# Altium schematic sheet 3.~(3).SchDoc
size 609 x 444 mm
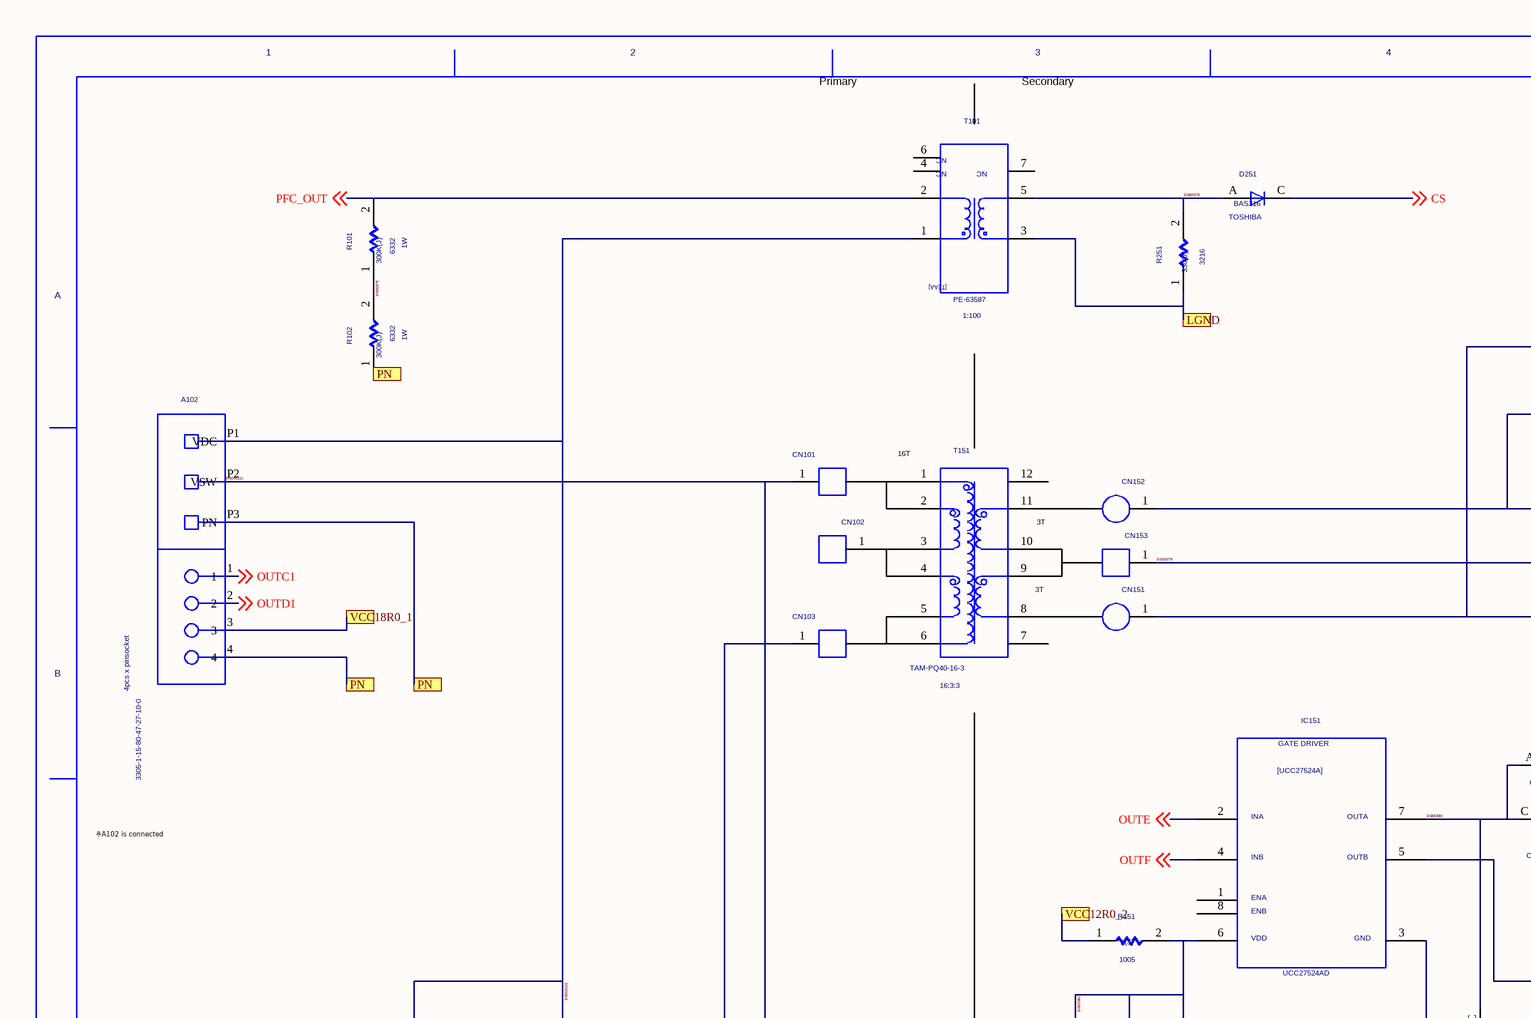
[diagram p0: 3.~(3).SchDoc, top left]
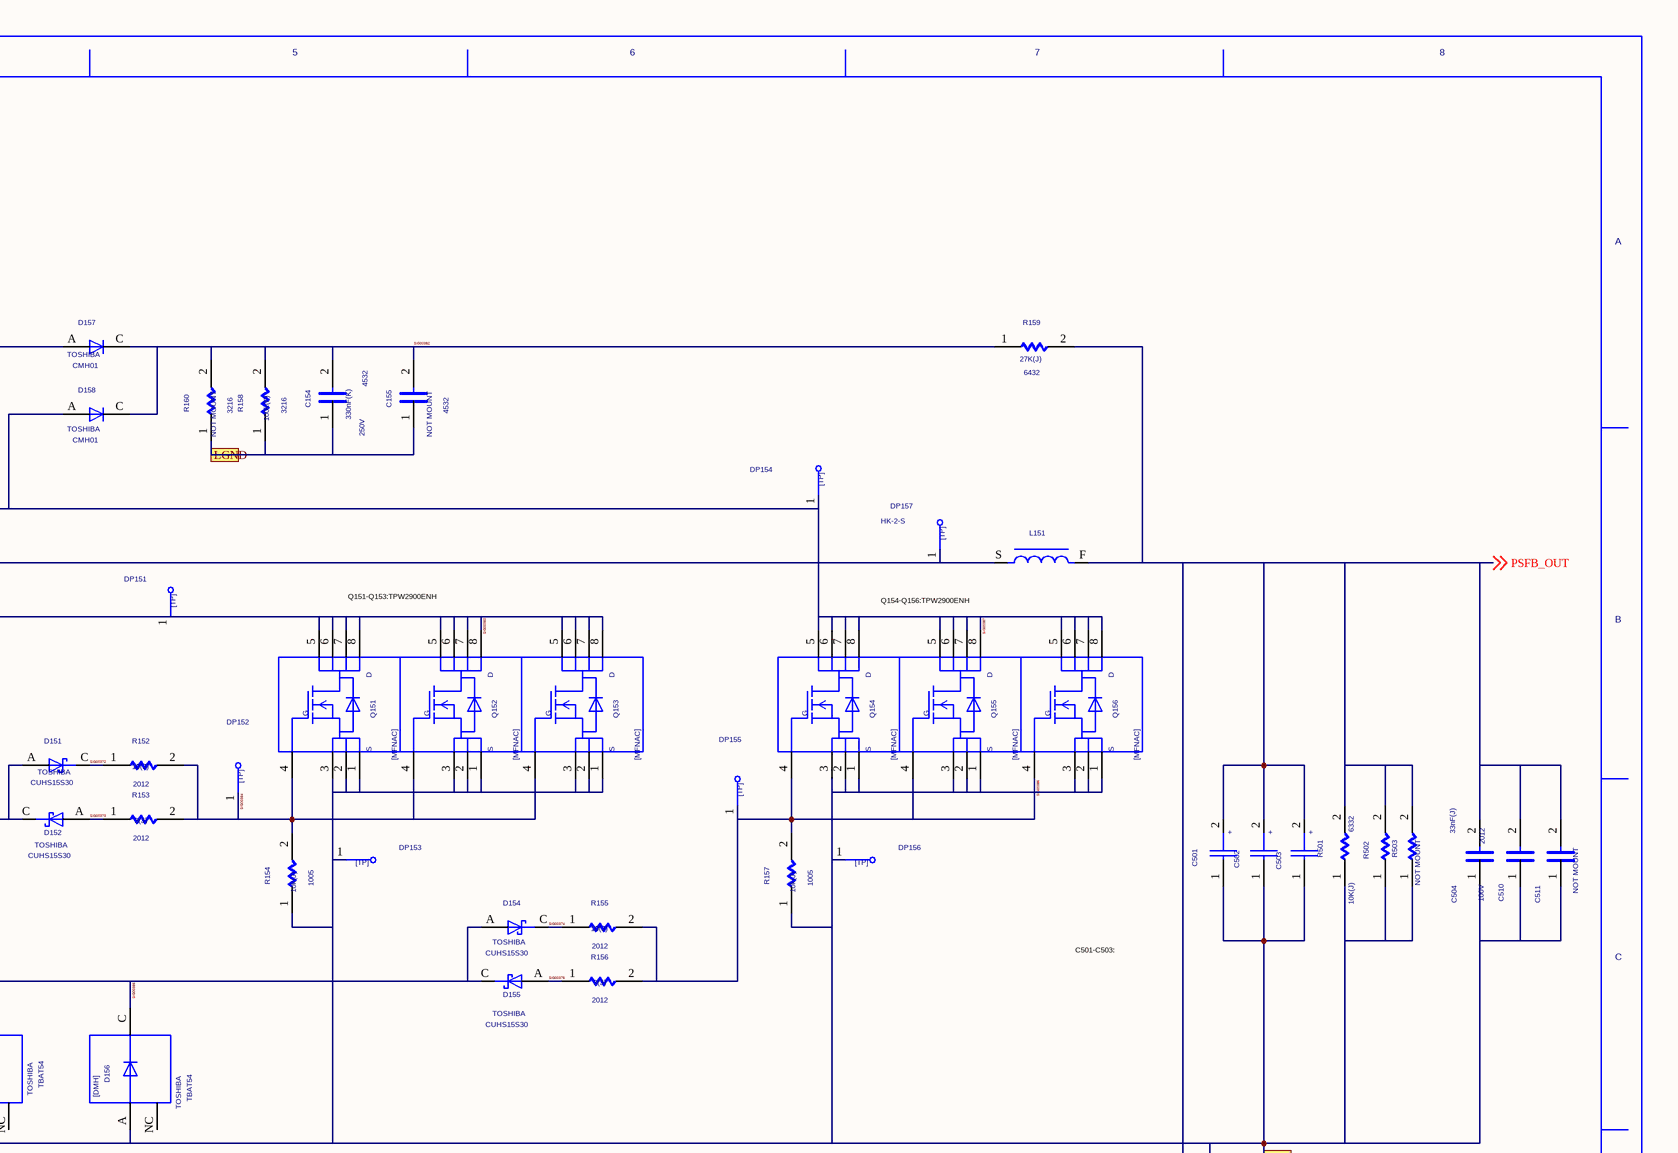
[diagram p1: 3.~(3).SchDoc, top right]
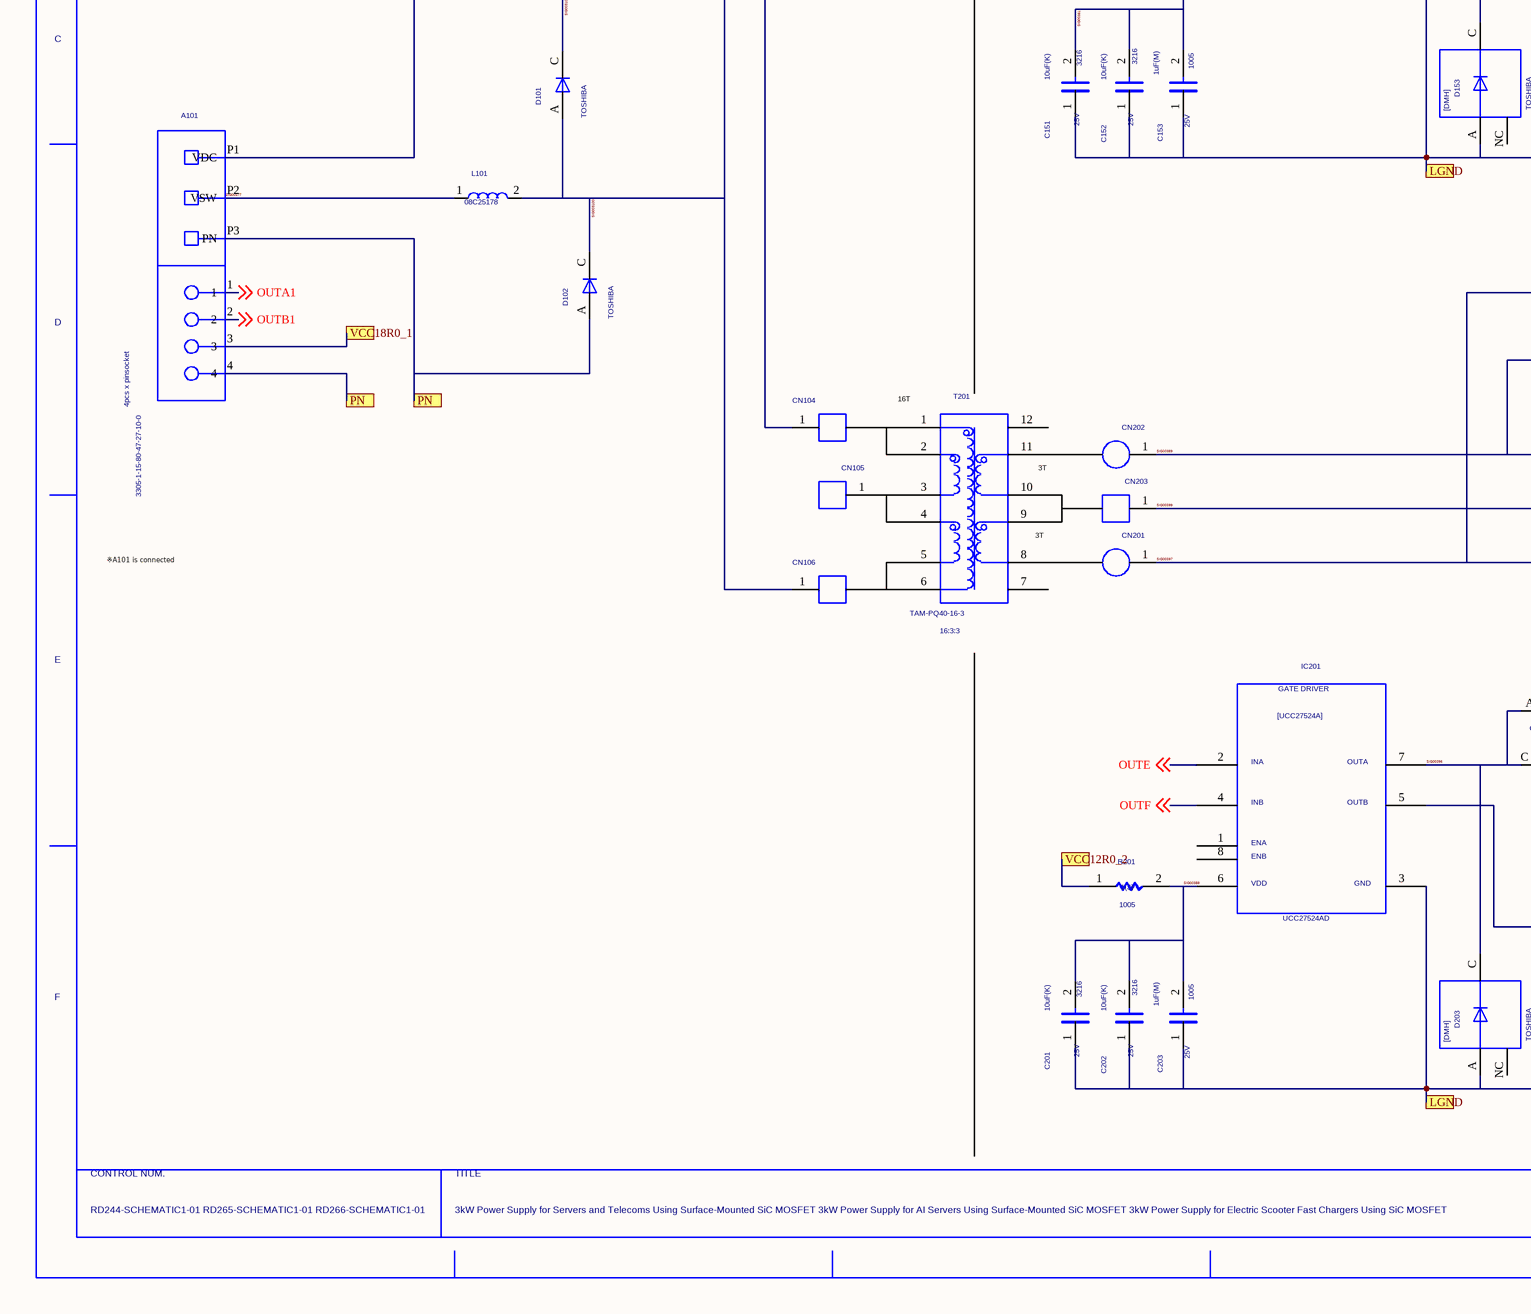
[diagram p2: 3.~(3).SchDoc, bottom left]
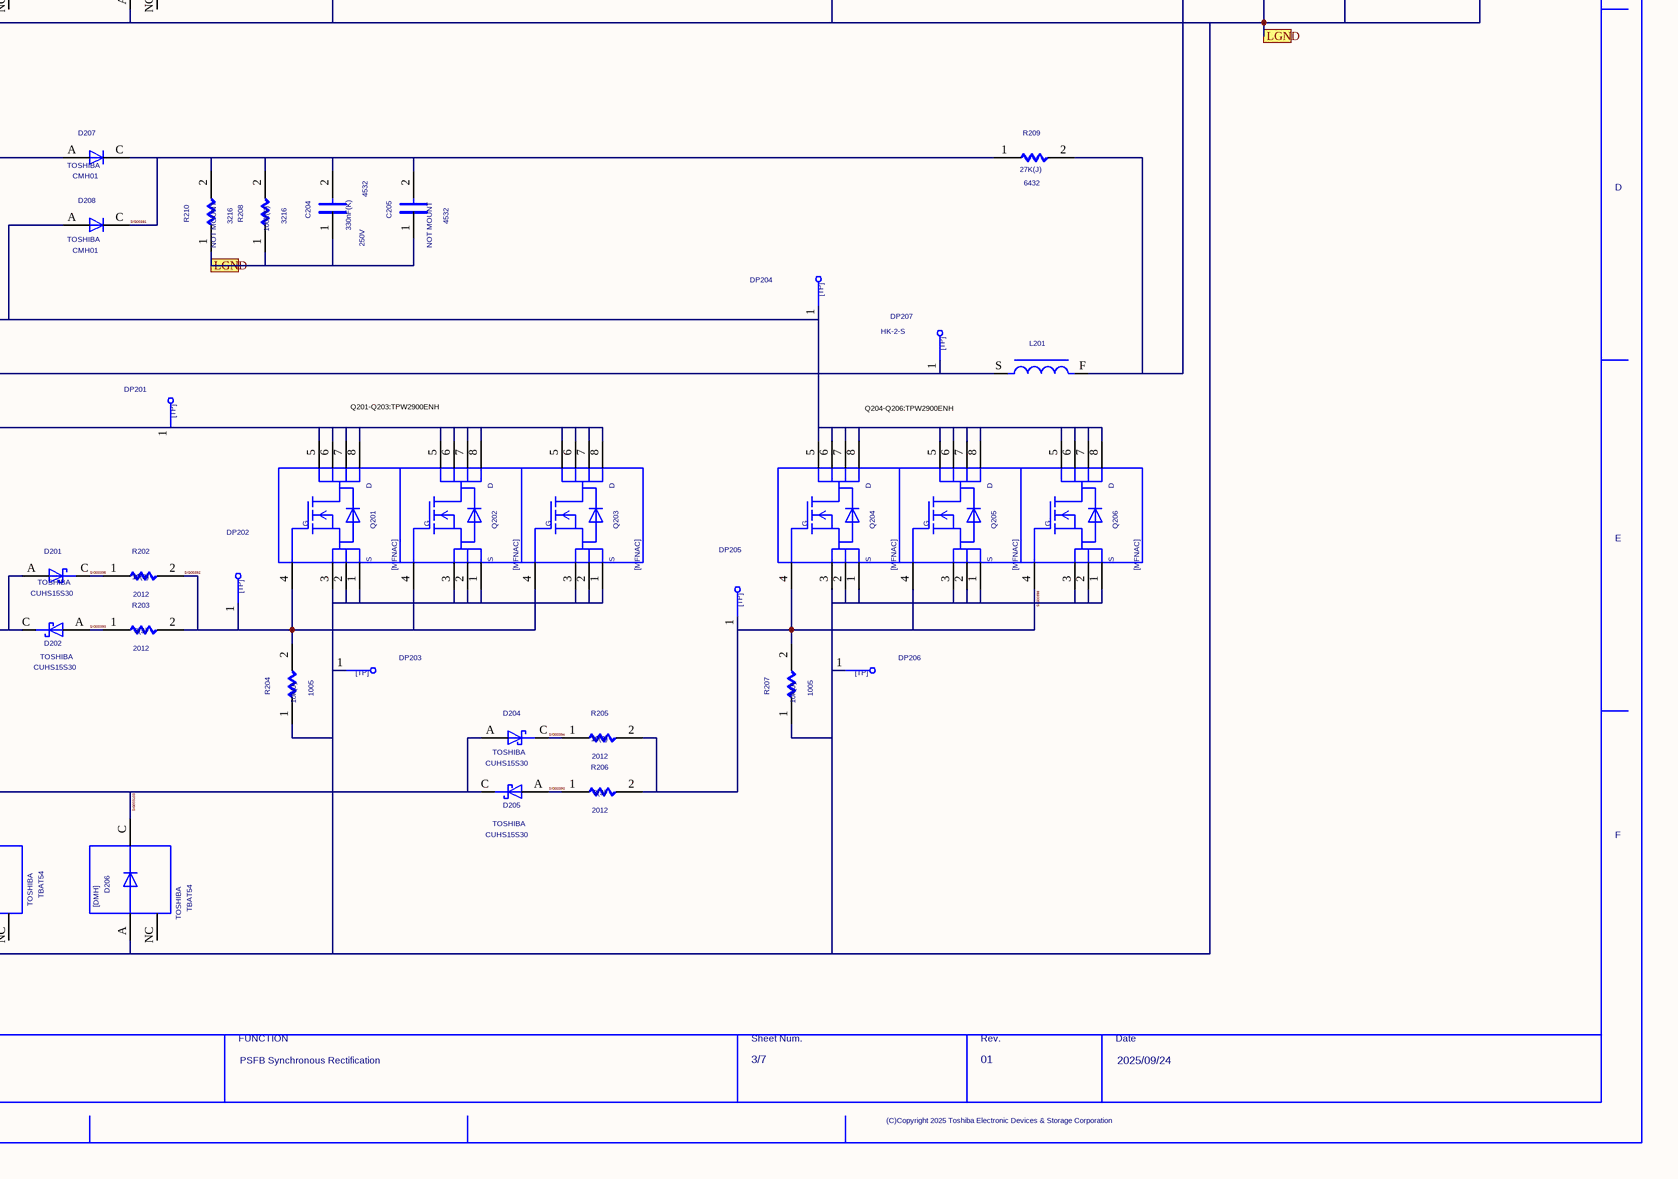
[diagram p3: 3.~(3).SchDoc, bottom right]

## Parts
A101  VAL3: 3305-1-15-80-47-27-10-0  VAL2: 4pcs x pinsocket  (hidden comment: RD-244_FB_Unit)
A102  VAL3: 3305-1-15-80-47-27-10-0  VAL2: 4pcs x pinsocket  (hidden comment: RD-244_FB_Unit)
C151  VAL1: 10uF(K)  VAL2: 25V  SIZECODESMD: 3216  (hidden comment: C)
C152  VAL1: 10uF(K)  VAL2: 25V  SIZECODESMD: 3216  (hidden comment: C)
C153  VAL1: 1uF(M)  VAL2: 25V  SIZECODESMD: 1005  (hidden comment: C)
C154  VAL1: 330nF(K)  VAL2: 250V  SIZECODESMD: 4532  (hidden comment: C)
C155  NOTMOUNT: NOT MOUNT  SIZECODESMD: 4532  (hidden comment: C)
C201  VAL1: 10uF(K)  VAL2: 25V  SIZECODESMD: 3216  (hidden comment: C)
C202  VAL1: 10uF(K)  VAL2: 25V  SIZECODESMD: 3216  (hidden comment: C)
C203  VAL1: 1uF(M)  VAL2: 25V  SIZECODESMD: 1005  (hidden comment: C)
C204  VAL1: 330nF(K)  VAL2: 250V  SIZECODESMD: 4532  (hidden comment: C)
C205  NOTMOUNT: NOT MOUNT  SIZECODESMD: 4532  (hidden comment: C)
C501  CP  (value not drawn)
C502  CP  (value not drawn)
C503  CP  (value not drawn)
C504  VAL1: 33nF(J)  VAL2: 100V  SIZECODESMD: 2012  (hidden comment: GRM21BC71E106KE01)
C510  NOTMOUNT: NOT MOUNT  (hidden comment: GRM21BC71E106KE01)
C511  GRM21BC71E106KE01  (value not drawn)
CN101  Longhole_2R5-5R5  (value not drawn)
CN102  Longhole_2R5-4R5  (value not drawn)
CN103  Longhole_2R5-5R5  (value not drawn)
CN104  Longhole_2R5-5R5  (value not drawn)
CN105  Longhole_2R5-4R5  (value not drawn)
CN106  Longhole_2R5-5R5  (value not drawn)
CN151  TH_phi_4R5  (value not drawn)
CN152  TH_phi_4R5  (value not drawn)
CN153  Longhole_4R5-8R5  (value not drawn)
CN201  TH_phi_4R5  (value not drawn)
CN202  TH_phi_4R5  (value not drawn)
CN203  Longhole_4R5-8R5  (value not drawn)
D101  USERCOMPTEXT3: TOSHIBA  (hidden comment: TRS8E65F)
D102  USERCOMPTEXT3: TOSHIBA  (hidden comment: TRS8E65F)
D151  USERCOMPTEXT3: TOSHIBA  (hidden comment: CUHS15S30)
D152  USERCOMPTEXT3: TOSHIBA  (hidden comment: CUHS15S30)
D153  USERCOMPTEXT3: TOSHIBA  VAL3: TBAT54  (hidden comment: DMH)
D154  USERCOMPTEXT3: TOSHIBA  (hidden comment: CUHS15S30)
D155  USERCOMPTEXT3: TOSHIBA  (hidden comment: CUHS15S30)
D156  USERCOMPTEXT3: TOSHIBA  VAL3: TBAT54  (hidden comment: DMH)
D157  USERCOMPTEXT3: TOSHIBA  VAL3: CMH01  (hidden comment: D)
D158  USERCOMPTEXT3: TOSHIBA  VAL3: CMH01  (hidden comment: D)
D201  USERCOMPTEXT3: TOSHIBA  (hidden comment: CUHS15S30)
D202  USERCOMPTEXT3: TOSHIBA  (hidden comment: CUHS15S30)
D203  USERCOMPTEXT3: TOSHIBA  VAL3: TBAT54  (hidden comment: DMH)
D204  USERCOMPTEXT3: TOSHIBA  (hidden comment: CUHS15S30)
D205  USERCOMPTEXT3: TOSHIBA  (hidden comment: CUHS15S30)
D206  USERCOMPTEXT3: TOSHIBA  VAL3: TBAT54  (hidden comment: DMH)
D207  USERCOMPTEXT3: TOSHIBA  VAL3: CMH01  (hidden comment: D)
D208  USERCOMPTEXT3: TOSHIBA  VAL3: CMH01  (hidden comment: D)
D251  USERCOMPTEXT3: TOSHIBA  VAL3: BAS316  (hidden comment: D)
DP151  TP  (value not drawn)
DP152  TP  (value not drawn)
DP153  TP  (value not drawn)
DP154  TP  (value not drawn)
DP155  TP  (value not drawn)
DP156  TP  (value not drawn)
DP157  VAL3: HK-2-S  (hidden comment: TP)
DP201  TP  (value not drawn)
DP202  TP  (value not drawn)
DP203  TP  (value not drawn)
DP204  TP  (value not drawn)
DP205  TP  (value not drawn)
DP206  TP  (value not drawn)
DP207  VAL3: HK-2-S  (hidden comment: TP)
IC151  VAL3: UCC27524AD  (hidden comment: L27524)
IC201  VAL3: UCC27524AD  (hidden comment: L27524)
L101  VAL3: 08C25178  (hidden comment: TMSD-Y3001)
L151  TAM-CTW32A6R5  (value not drawn)
L201  TAM-CTW32A6R5  (value not drawn)
Q151  TPH2R408QM_8PIN  (value not drawn)
Q152  TPH2R408QM_8PIN  (value not drawn)
Q153  TPH2R408QM_8PIN  (value not drawn)
Q154  TPH2R408QM_8PIN  (value not drawn)
Q155  TPH2R408QM_8PIN  (value not drawn)
Q156  TPH2R408QM_8PIN  (value not drawn)
Q201  TPH2R408QM_8PIN  (value not drawn)
Q202  TPH2R408QM_8PIN  (value not drawn)
Q203  TPH2R408QM_8PIN  (value not drawn)
Q204  TPH2R408QM_8PIN  (value not drawn)
Q205  TPH2R408QM_8PIN  (value not drawn)
Q206  TPH2R408QM_8PIN  (value not drawn)
R101  USERCOMPTEXT1: 300K(J)  USERCOMPTEXT2: 1W  SIZECODESMD: 6332  (hidden comment: R)
R102  USERCOMPTEXT1: 300K(J)  USERCOMPTEXT2: 1W  SIZECODESMD: 6332  (hidden comment: R)
R151  VAL1: 1(J)  SIZECODESMD: 1005  (hidden comment: R)
R152  VAL1: 10(J)  SIZECODESMD: 2012  (hidden comment: R)
R153  VAL1: 3(J)  SIZECODESMD: 2012  (hidden comment: R)
R154  VAL1: 10k(J)  SIZECODESMD: 1005  (hidden comment: R)
R155  VAL1: 10(J)  SIZECODESMD: 2012  (hidden comment: R)
R156  VAL1: 3(J)  SIZECODESMD: 2012  (hidden comment: R)
R157  VAL1: 10k(J)  SIZECODESMD: 1005  (hidden comment: R)
R158  VAL1: 100k(F)  SIZECODESMD: 3216  (hidden comment: R)
R159  USERCOMPTEXT1: 27K(J)  SIZECODESMD: 6432  (hidden comment: R)
R160  NOTMOUNT: NOT MOUNT  SIZECODESMD: 3216  (hidden comment: R)
R201  VAL1: 1(J)  SIZECODESMD: 1005  (hidden comment: R)
R202  VAL1: 10(J)  SIZECODESMD: 2012  (hidden comment: R)
R203  VAL1: 3(J)  SIZECODESMD: 2012  (hidden comment: R)
R204  VAL1: 10k(J)  SIZECODESMD: 1005  (hidden comment: R)
R205  VAL1: 10(J)  SIZECODESMD: 2012  (hidden comment: R)
R206  VAL1: 3(J)  SIZECODESMD: 2012  (hidden comment: R)
R207  VAL1: 10k(J)  SIZECODESMD: 1005  (hidden comment: R)
R208  VAL1: 100k(F)  SIZECODESMD: 3216  (hidden comment: R)
R209  USERCOMPTEXT1: 27K(J)  SIZECODESMD: 6432  (hidden comment: R)
R210  NOTMOUNT: NOT MOUNT  SIZECODESMD: 3216  (hidden comment: R)
R251  VAL1: 330(J)  SIZECODESMD: 3216  (hidden comment: R)
R501  USERCOMPTEXT1: 10K(J)  SIZECODESMD: 6332  (hidden comment: R)
R502  R  (value not drawn)
R503  NOTMOUNT: NOT MOUNT  (hidden comment: R)
T101  VAL1: 1:100  VAL3: PE-63587  (hidden comment: T2AA)
T151  VAL3: TAM-PQ40-16-3  USERCOMPTEXT1: 16:3:3  (hidden comment: T3_12V67A)
T201  VAL3: TAM-PQ40-16-3  USERCOMPTEXT1: 16:3:3  (hidden comment: T3_12V67A)
U?  DATE: 2025/09/24  DRAWINGNUMBER: RD244-SCHEMATIC1-01 / RD265-SCHEMATIC1-01 / RD266-SCHEMATIC1-01  TITLE: 3kW Power Supply for Servers and Telecoms Using Surface-Mounted SiC MOSFET / 3kW Power Supply for AI Servers Using Surface-Mounted SiC MOSFET / 3kW Power Supply for Electric Scooter Fast Chargers Using SiC MOSFET  FUNCTION: PSFB Synchronous Rectification  SHEETNUMBER: 3/7  REVISION: 01  (hidden comment: WAKU_DEF_A3_1)

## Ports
LGND, PN, VCC12R0_2, VCC18R0_1

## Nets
CS: D251.C ; off-sheet CS
LGND: C151.1 C152.1 C153.1 C154.1 C155.1 C201.1 C202.1 C203.1 C204.1 C205.1 C501.1 C502.1 C503.1 C504.1 C510.1 C511.1 D153.A D156.A D203.A D206.A DP153.1 DP156.1 DP203.1 DP206.1 IC151.3 IC201.3 Q151.1 Q151.2 Q151.3 Q152.1 Q152.2 Q152.3 Q153.1 Q153.2 Q153.3 Q154.1 Q154.2 Q154.3 Q155.1 Q155.2 Q155.3 Q156.1 Q156.2 Q156.3 Q201.1 Q201.2 Q201.3 Q202.1 Q202.2 Q202.3 Q203.1 Q203.2 Q203.3 Q204.1 Q204.2 Q204.3 Q205.1 Q205.2 Q205.3 Q206.1 Q206.2 Q206.3 R154.1 R157.1 R158.1 R160.1 R204.1 R207.1 R208.1 R210.1 R251.1 R501.1 R502.1 R503.1 T101.3 ; port LGND
OUTA1: A101.1 ; off-sheet OUTA1
OUTB1: A101.2 ; off-sheet OUTB1
OUTC1: A102.1 ; off-sheet OUTC1
OUTD1: A102.2 ; off-sheet OUTD1
OUTE: IC151.2 IC201.2 ; off-sheet OUTE
OUTF: IC151.4 IC201.4 ; off-sheet OUTF
PFC_OUT: R101.2 T101.2 ; off-sheet PFC_OUT
PN: A101.4 A101.P3(PN) A102.4 A102.P3(PN) D102.A R102.1 ; port PN
PSFB_OUT: C501.2 C502.2 C503.2 C504.2 C510.2 C511.2 L151.F L201.F R159.2 R209.2 R501.2 R502.2 R503.2 ; off-sheet PSFB_OUT
SIG00372: D151.C R152.1
SIG00373: D152.A R153.1
SIG00374: D154.C R155.1
SIG00375: D155.A R156.1
SIG00376: CN153.1 DP157.1 L151.S
SIG00377: A101.P2(VSW) L101.1
SIG00378: D251.A R251.2 T101.5
SIG00379: R101.1 R102.2
SIG00380: D151.A D152.C D153.C IC151.7
SIG00381: C151.2 C152.2 C153.2 IC151.6 R151.2
SIG00382: C154.2 C155.2 D157.C D158.C R158.2 R159.1 R160.2
SIG00383: CN151.1 D157.A DP151.1 Q151.5 Q151.6 Q151.7 Q151.8 Q152.5 Q152.6 Q152.7 Q152.8 Q153.5 Q153.6 Q153.7 Q153.8
SIG00384: DP152.1 Q151.4 Q152.4 Q153.4 R152.2 R153.2 R154.2
SIG00385: D154.A D155.C D156.C IC151.5
SIG00386: DP155.1 Q154.4 Q155.4 Q156.4 R155.2 R156.2 R157.2
SIG00387: CN152.1 D158.A DP154.1 Q154.5 Q154.6 Q154.7 Q154.8 Q155.5 Q155.6 Q155.7 Q155.8 Q156.5 Q156.6 Q156.7 Q156.8
SIG00388: C201.2 C202.2 C203.2 IC201.6 R201.2
SIG00389: CN202.1 D208.A DP204.1 Q204.5 Q204.6 Q204.7 Q204.8 Q205.5 Q205.6 Q205.7 Q205.8 Q206.5 Q206.6 Q206.7 Q206.8
SIG00390: D205.A R206.1
SIG00391: C204.2 C205.2 D207.C D208.C R208.2 R209.1 R210.2
SIG00392: DP202.1 Q201.4 Q202.4 Q203.4 R202.2 R203.2 R204.2
SIG00393: D202.A R203.1
SIG00394: D204.C R205.1
SIG00395: D201.C R202.1
SIG00396: D201.A D202.C D203.C IC201.7
SIG00397: CN201.1 D207.A DP201.1 Q201.5 Q201.6 Q201.7 Q201.8 Q202.5 Q202.6 Q202.7 Q202.8 Q203.5 Q203.6 Q203.7 Q203.8
SIG00398: DP205.1 Q204.4 Q205.4 Q206.4 R205.2 R206.2 R207.2
SIG00399: CN203.1 DP207.1 L201.S
SIG003100: CN103.1 CN106.1 D101.A D102.C L101.2
SIG003101: A102.P2(VSW) CN101.1 CN104.1
SIG003102: A101.P1(VDC) A102.P1(VDC) D101.C T101.1
SIG003103: D204.A D205.C D206.C IC201.5
VCC12R0_2: R151.1 R201.1 ; port VCC12R0_2
VCC18R0_1: A101.3 A102.3 ; port VCC18R0_1

Not connected (* = marked no-connect by the designer): CN102 1; CN105 1; D153 NC; D156 NC; D203 NC; D206 NC; IC151 1 8; IC201 1 8; T101 4 6 7; T151 1 2 3 4 5 6 7 8 9 10 11 12; T201 1 2 3 4 5 6 7 8 9 10 11 12

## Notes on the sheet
- Primary
- Secondary
- (near T151) 16T
- (near T151) 3T
- Q151-Q153:TPW2900ENH
- Q154-Q156:TPW2900ENH
- ※A102 is connected
  to CN701 and CN702 of RD244-SCHEMATICS3
- C501-C503:
- (near T201) 16T
- (near T201) 3T
- ※A101 is connected
  to CN701 and CN702 of RD244-SCHEMATICS3
- Q201-Q203:TPW2900ENH
- Q204-Q206:TPW2900ENH

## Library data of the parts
A101 A102 = RD-244_FB_UNIT: TIME: 11:34:46; UPDATEUSER: t4887876; UPDATETIME: 08:09:20; SAVECOUNT: 38; SAVEAREA0: -20981,-344,43891,33349; OriginalSymbolOrigin: (0,50800)
C151 C152 C201 C202 = C_Dup2: OriginalSymbolOrigin: (2540,7620); COMP: PRT_46; MAXGCOUNT: 1; SAVECOUNT: 0
C153 C203 = C_Dup2: OriginalSymbolOrigin: (2540,7620); COMP: PRT_52; MAXGCOUNT: 1; SAVECOUNT: 0
C154 C204 = C: SQ_PART_MODEL: CON_150N; OriginalSymbolOrigin: (2540,7620); GATENO: 1; ADSCNVFLAG: ON; ADSCOMPONENTNAME: C_4532; COMP: K0301583; CHIPSIZE: 1005; SAVECOUNT: 0
C155 C205 = C: SQ_PART_MODEL: CON_150N; VAL1: 330nF(K); VAL2: 250V; OriginalSymbolOrigin: (2540,7620); GATENO: 1; ADSCNVFLAG: ON; ADSCOMPONENTNAME: C_4532; COMP: K0301583; CHIPSIZE: 1005; SAVECOUNT: 0
C501-C503 = CP: SAVEAREA0: -1450,-153,20294,13055; SAVECOUNT: 52; TIME: 15:02:55; UPDATEUSER: fukuda-y; UPDATETIME: 16:13:42; VAL1: 330uF(M); VAL2: 63V; OriginalSymbolOrigin: (2540,10160); COMP: PRT_3; CHIPSIZE: D10xL22; MAXGCOUNT: 1; SIZECODESMD: DIP
C504 = GRM21BC71E106KE01: TIME: 10:25:11; UPDATEUSER: t4887876; UPDATETIME: 16:23:00; SAVECOUNT: 11; MAKER: Murata; OriginalSymbolOrigin: (2540,7620); CHIPSIZE: 1005; MAXGCOUNT: 1
C510 = GRM21BC71E106KE01: TIME: 10:25:11; UPDATEUSER: t4887876; UPDATETIME: 16:23:00; SAVECOUNT: 11; VAL1: 33nF(J); VAL2: 100V; MAKER: Murata; CHIPSET: 2012; OriginalSymbolOrigin: (2540,7620); CHIPSIZE: 1005; MAXGCOUNT: 1
C511 = GRM21BC71E106KE01: TIME: 10:25:11; UPDATEUSER: t4887876; UPDATETIME: 16:23:00; SAVECOUNT: 11; VAL1: 33nF(J); VAL2: 100V; MAKER: Murata; CHIPSET: 2012; NOTMOUNT: NOT MOUNT; OriginalSymbolOrigin: (2540,7620); CHIPSIZE: 1005; MAXGCOUNT: 1
CN101 CN103 CN104 CN106 = LONGHOLE_2R5-5R5: TIME: 17:17:39; UPDATEUSER: t4887876; UPDATETIME: 09:28:53; SAVECOUNT: 11; VAL3: PCB Pad; OriginalSymbolOrigin: (5080,5080)
CN102 CN105 = LONGHOLE_2R5-4R5: TIME: 17:17:39; UPDATEUSER: t4887876; UPDATETIME: 09:28:53; SAVECOUNT: 11; VAL3: PCB Pad; OriginalSymbolOrigin: (5080,5080)
CN151 CN152 CN201 CN202 = TH_PHI_4R5: TIME: 17:17:39; UPDATEUSER: t4887876; UPDATETIME: 10:35:58; SAVECOUNT: 11; VAL3: PCB Pad; OriginalSymbolOrigin: (5080,5080)
CN153 CN203 = LONGHOLE_4R5-8R5: TIME: 17:17:39; UPDATEUSER: t4887876; UPDATETIME: 09:28:53; SAVECOUNT: 12; VAL3: PCB Pad; OriginalSymbolOrigin: (5080,5080)
D101 D102 = TRS8E65F: SAVEAREA0: -225,-91,12804,7836; SAVECOUNT: 5; TIME: 14:49:55; UPDATEUSER: t6860224; UPDATETIME: 17:57:03; VAL3: TRS8E65H; OriginalSymbolOrigin: (5080,5080); VAL2: 650V,8A; MAXGCOUNT: 1
D151 D152 D154 D155 D201 D202 D204 D205 = CUHS15S30: SAVEAREA0: -4630,-153,17114,13055; TIME: 14:49:55; UPDATEUSER: t4887876; UPDATETIME: 17:19:09; SAVECOUNT: 10; OriginalSymbolOrigin: (5080,5080); USERCOMPTEXT2: 30V,1.5A
D153 D156 D203 D206 = DMH: SAVEAREA0: -4931,-287,27399,20979; TIME: 08:58:08; UPDATEUSER: kishi-s; UPDATETIME: 09:01:52; SAVECOUNT: 2; OriginalSymbolOrigin: (5080,17780); USERCOMPTEXT2: 30V,0.2A; COMP: PRT_25
D157 D158 D207 D208 = D_Dup1: SAVEAREA0: -225,-91,12804,7836; SAVECOUNT: 3; TIME: 14:49:55; UPDATEUSER: 19870035; UPDATETIME: 14:20:16; OriginalSymbolOrigin: (5080,5080); USERCOMPTEXT2: 200V,3A; COMP: PRT_14; MAXGCOUNT: 1
D251 = D_Dup1: SAVEAREA0: -225,-91,12804,7836; SAVECOUNT: 3; TIME: 14:49:55; UPDATEUSER: 19870035; UPDATETIME: 14:20:16; OriginalSymbolOrigin: (5080,5080); USERCOMPTEXT2: 80V,0.1A; COMP: PRT_27; MAXGCOUNT: 1
DP151-DP156 DP201-DP206 = TP: TIME: 16:12:21; UPDATEUSER: fukuda-y; UPDATETIME: 16:18:11; SAVECOUNT: 2; SAVEAREA0: -242,-92,12810,7836; OriginalSymbolOrigin: (0,7620); USERCOMPTEXT1: Φ1.5mm; COMP: DTP815
DP157 DP207 = TP: TIME: 16:12:21; UPDATEUSER: fukuda-y; UPDATETIME: 16:18:11; SAVECOUNT: 2; SAVEAREA0: -242,-92,12810,7836; OriginalSymbolOrigin: (0,7620); COMP: PRT_44
IC151 IC201 = L27524: SAVEAREA0: -24347,-591,50370,48694; SAVECOUNT: 22; TIME: 15:02:55; UPDATEUSER: cae; UPDATETIME: 14:54:38; OriginalSymbolOrigin: (7620,45720); COMP: PRT_63
L101 = TMSD-Y3001: VAL1: 13uH; TIME: 11:29:15; UPDATEUSER: t4887876; UPDATETIME: 13:47:51; SAVECOUNT: 2; VAL2: (Rated Current/Idc=0A); OriginalSymbolOrigin: (2540,5080)
L151 L201 = TAM-CTW32A6R5: SAVECOUNT: 8; SAVEAREA0: -384,-828,17939,11225; TIME: 16:55:46; UPDATEUSER: t4887876; UPDATETIME: 06:59:32; VAL1: 9.5uH; VAL2: 32A; MAKER: TAMURA; OriginalSymbolOrigin: (2540,5080); MAXGCOUNT: 1
Q151 Q152 Q154 Q201 Q202 Q204 = TPH2R408QM_8PIN: TIME: 18:29:30; UPDATEUSER: t4887876; UPDATETIME: 15:52:00; SAVECOUNT: 28; SAVEAREA0: -10143,-336,37609,28718; COMP: TPW2900ENH; VAL2: 120A; OriginalSymbolOrigin: (5080,25400); MAXGCOUNT: 1; USERCOMPTEXT3: TOSHIBA
Q153 Q156 Q203 Q206 = TPH2R408QM_8PIN: TIME: 18:29:30; UPDATEUSER: t4887876; UPDATETIME: 15:52:00; SAVECOUNT: 28; SAVEAREA0: -10143,-336,37609,28718; COMP: TPW2900ENH; VAL2: 120A; NOTMOUNT: MOUNT; OriginalSymbolOrigin: (5080,25400); MAXGCOUNT: 1; USERCOMPTEXT3: TOSHIBA
Q155 Q205 = TPH2R408QM_8PIN: TIME: 18:29:30; UPDATEUSER: t4887876; UPDATETIME: 15:52:00; SAVECOUNT: 28; SAVEAREA0: -10143,-336,37609,28718; COMP: TPW2900ENH; VAL1: 80V; VAL2: 120A; OriginalSymbolOrigin: (5080,25400); MAXGCOUNT: 1; USERCOMPTEXT3: TOSHIBA
R101 R102 = R_Dup1: SQ_PART_MODEL: RES_47K; NOTMOUNT: MOUNT; VAL1: 47k(J); OriginalSymbolOrigin: (5080,5080); MAXGCOUNT: 1; ADSCNVFLAG: ON; ADSCOMPONENTNAME: R_6332; COMP: GDM010001640; CHIPSIZE: 6432; SAVECOUNT: 0
R151 R154 R157 R201 R204 R207 = R_Dup2: VAL2: 63mW; OriginalSymbolOrigin: (5080,5080); COMP: GDM010004481; CHIPSIZE: 1608; MAXGCOUNT: 1; SAVECOUNT: 0
R152 R153 R155 R156 R202 R203 R205 R206 = R_Dup2: VAL2: 250mW; OriginalSymbolOrigin: (5080,5080); COMP: R2012; CHIPSIZE: 3216; MAXGCOUNT: 1; SAVECOUNT: 0
R158 R208 = R_Dup2: VAL2: 250mW; OriginalSymbolOrigin: (5080,5080); COMP: PRT_5; MAXGCOUNT: 1; ADSCOMPONENTNAME: R_3216; SAVECOUNT: 0
R159 R209 = R_Dup1: SQ_PART_MODEL: RES_47K; VAL2: 1W; VAL1: 47k(J); OriginalSymbolOrigin: (5080,5080); ADSCNVFLAG: ON; COMP: CRGH2512J620R; MAXGCOUNT: 1; SAVECOUNT: 0
R160 R210 = R_Dup2: VAL2: 250mW; VAL1: 100k(F); OriginalSymbolOrigin: (5080,5080); COMP: PRT_5; MAXGCOUNT: 1; ADSCOMPONENTNAME: R_3216; SAVECOUNT: 0
R251 = R_Dup2: SQ_PART_MODEL: RES_4.87K; VAL2: 250mW; OriginalSymbolOrigin: (5080,5080); COMP: PRT_5; CHIPSIZE: 1608; MAXGCOUNT: 1; ADSCNVFLAG: ON; ADSCOMPONENTNAME: R_3216; SAVECOUNT: 0
R501 = R_Dup1: SQ_PART_MODEL: RES_47K; VAL2: 1W; VAL1: 47k(J); OriginalSymbolOrigin: (5080,5080); ADSCNVFLAG: ON; ADSCOMPONENTNAME: R_6332; COMP: GDM010001640; CHIPSIZE: 6432; MAXGCOUNT: 1; SAVECOUNT: 0
R502 = R_Dup1: SQ_PART_MODEL: RES_47K; NOTMOUNT: NOT MOUNT; VAL2: 1W; VAL1: 47k(J); OriginalSymbolOrigin: (5080,5080); USERCOMPTEXT1: 10K(J); ADSCNVFLAG: ON; ADSCOMPONENTNAME: R_6332; SIZECODESMD: 6332; COMP: GDM010001640; CHIPSIZE: 6432; MAXGCOUNT: 1; SAVECOUNT: 0
R503 = R_Dup1: SQ_PART_MODEL: RES_47K; VAL2: 1W; VAL1: 47k(J); OriginalSymbolOrigin: (5080,5080); USERCOMPTEXT1: 10K(J); ADSCNVFLAG: ON; ADSCOMPONENTNAME: R_6332; SIZECODESMD: 6332; COMP: GDM010001640; CHIPSIZE: 6432; MAXGCOUNT: 1; SAVECOUNT: 0
T101 = T2AA: TIME: 11:34:46; UPDATEUSER: t4887876; UPDATETIME: 16:34:34; SAVECOUNT: 11; SAVEAREA0: -20981,-344,43891,33349; OriginalSymbolOrigin: (5080,30480); COMP: PRT_65; MAXGCOUNT: 1
T151 T201 = TAM-PQ40-20-3: UPDATEUSER: t4887876; UPDATETIME: 20:17:22; SAVECOUNT: 21; TIME: 16:40:06; SAVEAREA0: -9901,-21944,29587,7006; ORIGINALSYMBOLORIGIN: (0,0)
U? = WAKU_DEF_A3_1: PLOTTIME: HH:MM; SAVEAREA0: 96913,-567914,509243,-368858; TIME: 12:01:09; UPDATEUSER: t5459927; UPDATETIME: 13:12:48; SAVECOUNT: 3; ZONEOFFSETX: 36; ZONEOFFSETY: -24; OriginalSymbolOrigin: (12700,-12700); SHTSAVECOUNT: 272; DESIGNED: TOSHIBA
